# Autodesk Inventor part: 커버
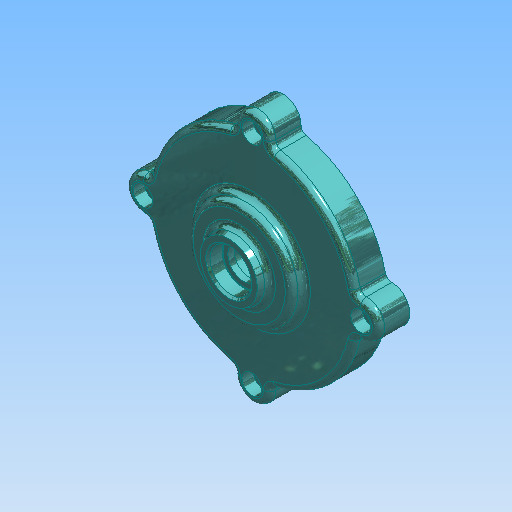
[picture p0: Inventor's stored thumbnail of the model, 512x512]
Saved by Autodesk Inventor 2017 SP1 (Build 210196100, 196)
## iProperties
Created: 2021-07
Part Number: 커버
Document SubType Name: 모델링
Designer: mdu
Material: 알루미늄 6061
Density: 2.71 g/cm^3
Mass: 196.657 g
Surface Area: 278.607 cm^2
Volume: 72.5671 cm^3
Appearance: 커버
변환 표준: STEP AP214IS
파일 이름: C:\Users\SeoGD\Desktop\?쒗뿕\而ㅻ쾭-1.stp
전처리기: Build: 253, Release: 2010 SP1 - Date: Wed 07/29/2009
전송 단위: 밀리미터
불확실성: 0.01
Author: mdu
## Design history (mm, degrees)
sketch "스케치1"
  geometry: L1 (0, 0)-(0, 26); L2 (50, 0)-(50, 15); L3 (50, 15)-(25, 15); L4 (25, 15)-(25, 21); L5 (25, 21)-(15, 21); L6 (15, 21)-(13.66, 26); L7 (13.66, 26)-(10, 26); L8 (50, 0)-(45, 0); L9 (45, 0)-(45, 10); L10 (45, 10)-(14.5, 10); L11 (14.5, 10)-(13.266, 3); L12 (13.266, 3)-(11, 3); L13 (11, 3)-(11, 16); L14 (11, 16)-(7.5, 16); L15 (7.5, 16)-(7.5, 19); L16 (7.5, 19)-(10, 19); L17 (10, 19)-(10, 26)
  constraints: 34 end point, 10 parallel, 2 perpendicular, 2 point on line, 1 vertical
  dimensions: "d11" = 100 diameter of L2 L1; "d12" = 22 diameter of L13 L1; "d13" = 90 diameter of L9 L1; "d14" = 15 distance between parallel lines of L3 L8; "d15" = 10 distance between parallel lines of L8 L10; "d16" = 29 diameter of L10.end L1; "d17" = 100 deg angle of L11 L10; "d18" = 7 distance between parallel lines of L12 L10; "d19" = 13 distance between parallel lines of L14 L12; "d20" = 3 distance between parallel lines of L16 L14; "d21" = 15 diameter of L15 L1; "d22" = 20 diameter of L17 L1; "d23" = 30 diameter of L5.end L1; "d24" = 6 distance between parallel lines of L5 L3; "d25" = 50 diameter of L4 L1; "d26" = 105 deg angle of L5 L6; "d50" = 26 distance of L1.start L1.end
revolve "회전1" sketch "스케치1" stored, may be unused: angle "d27" = 90 deg
sketch "스케치2" dims "d29" = 104
  geometry: A1 r 8.5 centre (0, 52) between (8.074, 49.344) and (-8.074, 49.344); A2 r 50 centre (0, 0) between (-8.074, 49.344) and (8.074, 49.344) reference; 2 further points
  constraints: 4 point on circle, 2 vertical alignment, 1 centre point, 1 coincident, 2 other
  dimensions: "d28" = 17 diameter of A1
extrude "돌출1" join sketch "스케치2" stored distance "d30" = 10; taper "d31" = 0 deg
fillet "모깎기3" dims "d32" = 3
fillet "모깎기4" dims "d45" = 3, "d46" = 0.2
chamfer "모따기1" distance "d47" = 1; stored, may be unused: second distance "d48" = 2, angle "d49" = 45 deg
hole "구멍2" diameter "d38" = 5.5; stored, may be unused: countersink angle "d42" = 90 deg, drill point angle "d44" = 118 deg; dims "d36" = 10, "d37" = 10, "d39" = 6, "d40" = 9.5, "d41" = 5.4, "d43" = 8
node "솔리드1"
node "솔리드 본체"
node "곡면 본체"
pattern_circular "원형 패턴1" dims angle "d34" = 360 deg
pattern_circular "원형 패턴2" dims angle "d52" = 360 deg
node "솔리드2"
